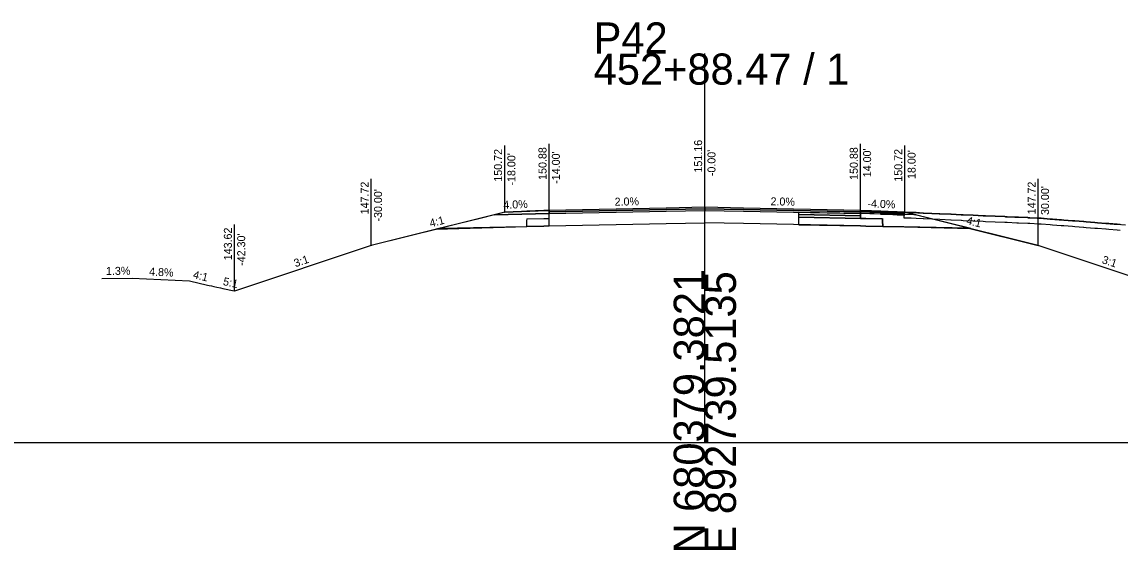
# Model space of a CAD drawing. Extents: x -26 to 4403, y -13 to 9578.
# Drawn here: x 188.6 to 287.4, y 1490.3 to 1537.8 of the extents above; entities that cross this region are included whole.
import ezdxf

# ---------------------------------------------------------------- set-up
doc = ezdxf.new("R2010")
doc.units = 0
for name, color, linetype in [('_CIVIL_CONSTRUCTION', 7, 'Continuous'), ('ASPHALT_19MM1', 7, 'Continuous'), ('ASPHALT_19MM2', 7, 'Continuous'), ('ASPHALT_9_5MM1', 7, 'Continuous'), ('CONST_DCH', 7, 'Continuous'), ('CONST_LV3', 7, 'Continuous'), ('Default', 7, 'Continuous'), ('DTM_CORRIDOR', 7, 'Continuous'), ('DTM_P_FINISHED_GRADE', 7, 'Continuous'), ('DTM_TEMP_DROP', 7, 'Continuous'), ('DTM_X_GROUND', 7, 'Continuous'), ('SLOPE_STAKES_FILL', 7, 'Continuous'), ('XS_CELL', 7, 'Continuous'), ('XS_M_EXCAVATION_LIMITS', 7, 'Continuous'), ('XS_P_ASPHALT', 7, 'Continuous'), ('XS_P_CRUSHED_STONE', 7, 'Continuous'), ('XS_P_DR_ASPHALT', 7, 'Continuous'), ('XS_P_DR_ASPHALT_B', 7, 'Continuous'), ('XS_P_DR_GRAVEL', 7, 'Continuous'), ('XS_P_GROUND', 7, 'Continuous'), ('XS_P_SHOULDER', 7, 'Continuous'), ('XS_P_SUBGRADE_GRANULAR', 7, 'Continuous'), ('XS_P_TX_CLEARZONE', 7, 'Continuous'), ('XS_P_TX_FS_BS', 7, 'Continuous')]:
    doc.layers.add(name, color=color, linetype=linetype)

msp = doc.modelspace()

# ---------------------------------------------------------------- linework, layer by layer
at = {"layer": 'ASPHALT_19MM1'}
msp.add_lwpolyline([(258.46, 1520.51), (264, 1520.399), (264, 1520.54), (264, 1520.587), (258.46, 1520.698)], dxfattribs=at)
at = {"layer": 'ASPHALT_19MM2'}
msp.add_lwpolyline([(258.46, 1520.26), (264, 1520.149), (264, 1520.337), (264, 1520.399), (258.46, 1520.51)], dxfattribs=at)
at = {"layer": 'ASPHALT_9_5MM1'}
for points in [[(246.532, 1521.089), (236, 1520.878), (236, 1520.848), (236, 1520.753), (246.532, 1520.964), (250, 1521.033), (250, 1521.128), (250, 1521.158), (246.532, 1521.089)], [(253.468, 1521.089), (250, 1521.158), (250, 1521.128), (250, 1521.033), (253.468, 1520.964), (264, 1520.753), (264, 1520.848), (264, 1520.878), (253.468, 1521.089)]]:
    msp.add_lwpolyline(points, dxfattribs=at)
at = {"layer": 'CONST_LV3'}
for points in [[(264, 1520.878), (264, 1520.878), (264.855, 1520.844), (264.916, 1520.842), (264.939, 1520.841), (265.777, 1520.807), (265.788, 1520.807), (265.833, 1520.805), (265.864, 1520.804), (266.708, 1520.77), (266.749, 1520.768), (266.782, 1520.767), (267.626, 1520.733), (267.665, 1520.731), (267.7, 1520.73), (268.544, 1520.696), (269.159, 1520.659), (270.13, 1520.617), (271.083, 1520.577), (271.198, 1520.569), (272.14, 1520.529), (273.063, 1520.489), (273.22, 1520.48), (274.133, 1520.441), (275.027, 1520.402), (275.224, 1520.392), (276.109, 1520.354), (276.976, 1520.316), (277.05, 1520.313), (277.901, 1520.276), (278.053, 1520.269), (278.209, 1520.263), (279.057, 1520.226), (279.887, 1520.19), (280.061, 1520.182), (280.88, 1520.118), (281.065, 1520.104), (281.873, 1520.041), (282.069, 1520.026), (282.866, 1519.963), (283.073, 1519.947), (283.283, 1519.931), (284.076, 1519.869), (284.298, 1519.851), (285.08, 1519.79), (285.845, 1519.73), (286.084, 1519.712), (286.838, 1519.653), (287.088, 1519.633), (287.831, 1519.575)], [(226.28, 1519.288), (220, 1517.718)], [(273.72, 1519.288), (280, 1517.718)]]:
    msp.add_lwpolyline(points, dxfattribs=at)
at = {"layer": 'Default'}
for points in [[(246.532, 1520.964), (236, 1520.753), (236, 1520.712), (236, 1520.587), (246.532, 1520.798), (250, 1520.867), (250, 1520.992), (250, 1521.033), (246.532, 1520.964)], [(253.468, 1520.964), (250, 1521.033), (250, 1520.992), (250, 1520.867), (253.468, 1520.798), (264, 1520.587), (264, 1520.712), (264, 1520.753), (253.468, 1520.964)]]:
    msp.add_lwpolyline(points, dxfattribs=at)
at = {"layer": 'DTM_P_FINISHED_GRADE'}
for points in [[(264, 1520.878), (264, 1520.878), (264.855, 1520.844), (264.916, 1520.842), (264.939, 1520.841), (265.777, 1520.807), (265.788, 1520.807), (265.833, 1520.805), (266.115, 1520.791), (266.481, 1520.779), (267.318, 1520.745), (268, 1520.718)], [(267.906, 1520.722), (267.907, 1520.722), (268, 1520.718), (268.544, 1520.696), (268.551, 1520.696), (269.006, 1520.678), (269.654, 1520.644), (269.666, 1520.644), (270.422, 1520.612), (270.434, 1520.612), (271.15, 1520.582), (272.14, 1520.529), (272.154, 1520.528), (273.063, 1520.489), (273.077, 1520.489), (273.234, 1520.48), (274.133, 1520.441), (274.147, 1520.44), (275.027, 1520.402), (275.041, 1520.402), (275.237, 1520.392), (276.109, 1520.354), (276.123, 1520.353), (276.976, 1520.316), (277.05, 1520.313), (277.063, 1520.312), (277.207, 1520.306), (278.053, 1520.269), (278.066, 1520.269), (278.222, 1520.262), (279.057, 1520.226), (279.07, 1520.225), (279.237, 1520.218), (280.061, 1520.182), (280.074, 1520.182), (280.251, 1520.168), (281.065, 1520.104), (281.077, 1520.103), (281.266, 1520.088), (282.069, 1520.026), (282.081, 1520.025), (282.281, 1520.009), (283.073, 1519.947), (283.085, 1519.946), (283.296, 1519.93), (284.076, 1519.869), (284.088, 1519.868), (284.31, 1519.85), (285.08, 1519.79), (285.092, 1519.789), (285.325, 1519.771), (286.084, 1519.712), (286.096, 1519.711), (286.34, 1519.691), (287.088, 1519.633), (287.099, 1519.632), (287.355, 1519.612)]]:
    msp.add_lwpolyline(points, dxfattribs=at)
at = {"layer": 'DTM_X_GROUND'}
msp.add_lwpolyline([(195.761, 1514.758), (198.481, 1514.794), (203.63, 1514.547), (205.254, 1514.161), (205.421, 1514.124), (205.616, 1514.081), (205.842, 1514.031), (206.108, 1513.973), (206.426, 1513.903), (206.432, 1513.901), (206.649, 1513.854), (207.651, 1513.635), (207.659, 1513.632), (207.679, 1513.624), (207.694, 1513.619), (207.696, 1513.618)], dxfattribs=at)
at = {"layer": 'XS_CELL'}
for p, q in [((250, 1500), (250, 1535)), ((0, 1500), (250, 1500)), ((250, 1500), (400, 1500))]:
    msp.add_line(p, q, dxfattribs=at)
at = {"layer": 'XS_M_EXCAVATION_LIMITS'}
for p, q in [((236, 1519.483), (236, 1520.587)), ((258.46, 1519.594), (258.46, 1520.698))]:
    msp.add_line(p, q, dxfattribs=at)
at = {"layer": 'XS_P_ASPHALT'}
msp.add_lwpolyline([(258.46, 1520.26), (264, 1520.149), (264, 1520.698), (264, 1520.878), (253.468, 1521.089), (250, 1521.158), (246.532, 1521.089)], dxfattribs=at)
at = {"layer": 'XS_P_CRUSHED_STONE'}
for points in [[(233.505, 1520.779), (232, 1520.718), (231.771, 1520.661), (231.075, 1520.487), (234.78, 1520.562), (236, 1520.587), (236, 1520.806), (236, 1520.878), (235.505, 1520.859), (234, 1520.798), (233.505, 1520.779)], [(264.495, 1519.473), (266, 1519.443), (265.996, 1519.944), (265.995, 1520.109), (264.494, 1520.139), (264, 1520.149), (258.46, 1520.26)], [(266.495, 1520.779), (268, 1520.718), (268.229, 1520.661), (268.925, 1520.487), (265.22, 1520.562), (264, 1520.587), (264, 1520.806), (264, 1520.878), (264.495, 1520.859), (266, 1520.798), (266.495, 1520.779)], [(235.505, 1519.473), (234, 1519.443), (234.004, 1519.944), (234.005, 1520.109), (235.506, 1520.139), (236, 1520.149), (236.033, 1520.15)], [(236, 1519.483), (235.505, 1519.473)], [(258.46, 1519.594), (264, 1519.483), (264.495, 1519.473)]]:
    msp.add_lwpolyline(points, dxfattribs=at)
at = {"layer": 'XS_P_DR_ASPHALT'}
msp.add_lwpolyline([(264, 1520.878), (264, 1520.753), (264, 1520.753), (264.855, 1520.719), (264.916, 1520.717), (264.939, 1520.716), (265.777, 1520.682), (265.788, 1520.682), (265.833, 1520.68), (266.115, 1520.666), (266.481, 1520.654), (267.318, 1520.62), (268, 1520.593), (268, 1520.593), (268, 1520.718), (268, 1520.718), (267.318, 1520.745), (266.481, 1520.779), (266.115, 1520.791), (265.833, 1520.805), (265.788, 1520.807), (265.777, 1520.807), (264.939, 1520.841), (264.916, 1520.842), (264.855, 1520.844), (264, 1520.878), (264, 1520.878)], dxfattribs=at)
at = {"layer": 'XS_P_DR_ASPHALT_B'}
msp.add_lwpolyline([(264, 1520.753), (264, 1520.628), (264, 1520.628), (264.855, 1520.594), (264.916, 1520.592), (264.939, 1520.591), (265.777, 1520.557), (265.788, 1520.557), (265.833, 1520.555), (266.115, 1520.541), (266.481, 1520.529), (267.318, 1520.495), (268, 1520.468), (268, 1520.468), (268, 1520.593), (268, 1520.593), (267.318, 1520.62), (266.481, 1520.654), (266.115, 1520.666), (265.833, 1520.68), (265.788, 1520.682), (265.777, 1520.682), (264.939, 1520.716), (264.916, 1520.717), (264.855, 1520.719), (264, 1520.753), (264, 1520.753)], dxfattribs=at)
at = {"layer": 'XS_P_DR_GRAVEL'}
for points in [[(267.906, 1520.722), (267.906, 1520.222), (267.907, 1520.222), (268, 1520.218), (268, 1520.218), (268.544, 1520.196), (268.551, 1520.196), (269.006, 1520.178), (269.654, 1520.144), (269.666, 1520.144), (270.422, 1520.112), (270.434, 1520.112), (271.15, 1520.082), (272.14, 1520.029), (272.154, 1520.028), (273.063, 1519.989), (273.077, 1519.989), (273.234, 1519.98), (274.133, 1519.941), (274.147, 1519.94), (275.027, 1519.902), (275.041, 1519.902), (275.237, 1519.892), (276.109, 1519.854), (276.123, 1519.853), (276.976, 1519.816), (277.05, 1519.813), (277.063, 1519.812), (277.207, 1519.806), (278.053, 1519.769), (278.066, 1519.769), (278.222, 1519.762), (279.057, 1519.726), (279.07, 1519.725), (279.237, 1519.718), (280.061, 1519.682), (280.074, 1519.682), (280.251, 1519.668), (281.065, 1519.604), (281.077, 1519.603), (281.266, 1519.588), (282.069, 1519.526), (282.081, 1519.525), (282.281, 1519.509), (283.073, 1519.447), (283.085, 1519.446), (283.296, 1519.43), (284.076, 1519.369), (284.088, 1519.368), (284.31, 1519.35), (285.08, 1519.29), (285.092, 1519.289), (285.325, 1519.271), (286.084, 1519.212), (286.096, 1519.211), (286.34, 1519.191), (287.088, 1519.133), (287.099, 1519.132), (287.355, 1519.112)], [(287.355, 1519.612), (287.099, 1519.632), (287.088, 1519.633), (286.34, 1519.691), (286.096, 1519.711), (286.084, 1519.712), (285.325, 1519.771), (285.092, 1519.789), (285.08, 1519.79), (284.31, 1519.85), (284.088, 1519.868), (284.076, 1519.869), (283.296, 1519.93), (283.085, 1519.946), (283.073, 1519.947), (282.281, 1520.009), (282.081, 1520.025), (282.069, 1520.026), (281.266, 1520.088), (281.077, 1520.103), (281.065, 1520.104), (280.251, 1520.168), (280.074, 1520.182), (280.061, 1520.182), (279.237, 1520.218), (279.07, 1520.225), (279.057, 1520.226), (278.222, 1520.262), (278.066, 1520.269), (278.053, 1520.269), (277.207, 1520.306), (277.063, 1520.312), (277.05, 1520.313), (276.976, 1520.316), (276.123, 1520.353), (276.109, 1520.354), (275.237, 1520.392), (275.041, 1520.402), (275.027, 1520.402), (274.147, 1520.44), (274.133, 1520.441), (273.234, 1520.48), (273.077, 1520.489), (273.063, 1520.489), (272.154, 1520.528), (272.14, 1520.529), (271.15, 1520.582), (270.434, 1520.612), (270.422, 1520.612), (269.666, 1520.644), (269.654, 1520.644), (269.006, 1520.678), (268.551, 1520.696), (268.544, 1520.696), (268, 1520.718), (268, 1520.718), (267.907, 1520.722), (267.906, 1520.722)]]:
    msp.add_lwpolyline(points, dxfattribs=at)
at = {"layer": 'XS_P_GROUND'}
for points in [[(232, 1520.718), (220, 1517.718), (207.696, 1513.618)], [(292.299, 1513.619), (289.249, 1514.636), (280, 1517.718), (270.973, 1519.975), (268, 1520.718)]]:
    msp.add_lwpolyline(points, dxfattribs=at)
at = {"layer": 'XS_P_SHOULDER'}
for points in [[(232, 1520.718), (235.009, 1520.839), (236, 1520.878)], [(268, 1520.718), (264.991, 1520.839), (264, 1520.878)]]:
    msp.add_lwpolyline(points, dxfattribs=at)
at = {"layer": 'XS_P_SUBGRADE_GRANULAR'}
for points in [[(236, 1520.479), (236, 1520.587), (234.78, 1520.562), (231.075, 1520.487), (229.779, 1520.163), (225.843, 1519.179), (231.979, 1519.378), (234, 1519.443), (234.004, 1519.944), (234.005, 1520.109), (235.506, 1520.139), (236, 1520.149), (236, 1520.479)], [(264, 1520.479), (264, 1520.149), (264.494, 1520.139), (265.995, 1520.109), (265.996, 1519.944), (266, 1519.443), (267.964, 1519.392), (273.927, 1519.237), (270.164, 1520.177), (268.925, 1520.487), (265.22, 1520.562), (264, 1520.587), (264, 1520.479)], [(226.28, 1519.288), (232.087, 1519.405), (234, 1519.443), (235.505, 1519.473), (236, 1519.483)], [(236, 1519.483), (246.532, 1519.693), (250, 1519.763)], [(264, 1519.483), (253.468, 1519.693), (250, 1519.763)], [(273.72, 1519.288), (267.913, 1519.405), (266, 1519.443), (264.495, 1519.473), (264, 1519.483)]]:
    msp.add_lwpolyline(points, dxfattribs=at)
at = {"layer": 'XS_P_TX_CLEARZONE'}
for p, q in [((250, 1521.158), (250, 1527.158)), ((232, 1520.718), (232, 1526.718)), ((236, 1520.878), (236, 1526.878)), ((264, 1520.878), (264, 1526.878)), ((268, 1520.718), (268, 1526.718)), ((220, 1517.718), (220, 1523.718)), ((280, 1517.718), (280, 1523.718)), ((207.696, 1513.618), (207.696, 1519.618)), ((207.696, 1513.618), (207.696, 1519.618))]:
    msp.add_line(p, q, dxfattribs=at)

# ---------------------------------------------------------------- texts
at = {"layer": '_CIVIL_CONSTRUCTION'}
for p in [(249.961, 1521.098), (231.036, 1520.427), (233.961, 1520.738), (235.961, 1520.818), (263.961, 1520.818), (268.886, 1520.427), (233.966, 1520.049), (265.955, 1520.049)]:
    msp.add_text('X', height=0.12, dxfattribs=at).set_placement(p)
at = {"layer": 'CONST_DCH'}
msp.add_text('X', height=0.12, dxfattribs=at).set_placement((207.657, 1513.558))
at = {"layer": 'DTM_CORRIDOR'}
msp.add_text('X', height=0.12, dxfattribs=at).set_placement((207.657, 1513.558))
at = {"layer": 'DTM_TEMP_DROP'}
for p in [(231.961, 1520.658), (267.961, 1520.658)]:
    msp.add_text('X', height=0.12, dxfattribs=at).set_placement(p)
at = {"layer": 'SLOPE_STAKES_FILL'}
for p in [(219.961, 1517.658), (279.961, 1517.658)]:
    msp.add_text('X', height=0.12, dxfattribs=at).set_placement(p)
at = {"layer": 'XS_CELL'}
for s, p in [('P42', (240, 1535)), ('452+88.47 / 1', (240, 1532.2))]:
    msp.add_text(s, height=2.8, dxfattribs=at).set_placement(p)
for s, p in [('N 680379.3821', (250, 1490)), ('E 892739.5135', (252.8, 1490))]:
    msp.add_text(s, height=2.8, rotation=90, dxfattribs=at).set_placement(p)
at = {"layer": 'XS_P_TX_CLEARZONE'}
for s, p in [('151.16', (249.76, 1524.286)), ('150.72', (231.76, 1523.466)), ('150.88', (235.76, 1523.626)), ("-14.00'", (236.96, 1523.275)), ("-0.00'", (250.96, 1523.963)), ('150.88', (263.76, 1523.626)), ("14.00'", (264.96, 1523.864)), ('150.72', (267.76, 1523.466)), ("18.00'", (268.96, 1523.704)), ("-18.00'", (232.96, 1523.115)), ('147.72', (219.76, 1520.523)), ('147.72', (279.76, 1520.523)), ("-30.00'", (220.96, 1519.876)), ("30.00'", (280.96, 1520.466)), ('143.62', (207.456, 1516.388)), ('143.62', (207.456, 1516.388)), ("-42.30'", (208.656, 1515.889)), ("-42.30'", (208.656, 1515.889))]:
    msp.add_text(s, height=0.72, rotation=90, dxfattribs=at).set_placement(p)
at = {"layer": 'XS_P_TX_FS_BS'}
for s, rotation, p in [('4.0%', 2.29061, (231.887, 1521.014)), ('2.0%', 1.14576, (241.892, 1521.296)), ('2.0%', 358.85424, (255.904, 1521.34)), ('-4.0%', 357.70939, (264.616, 1521.154)), ('4:1', 14.03624, (225.333, 1519.361)), ('4:1', 345.96376, (273.479, 1519.658)), ('3:1', 18.43323, (213.172, 1515.759)), ('3:1', 341.56677, (285.663, 1516.147)), ('1.3%', 0.74702, (196.134, 1515.063)), ('1.3%', 0.74702, (196.134, 1515.063)), ('4.8%', 357.25346, (199.998, 1515.021)), ('4.8%', 357.25346, (199.998, 1515.021)), ('4:1', 346.62922, (203.916, 1514.787)), ('4:1', 346.62922, (203.916, 1514.787)), ('5:1', 347.67933, (206.616, 1514.168)), ('5:1', 347.67933, (206.616, 1514.168))]:
    msp.add_text(s, height=0.72, rotation=rotation, dxfattribs=at).set_placement(p)

doc.saveas('drawing.dxf')
